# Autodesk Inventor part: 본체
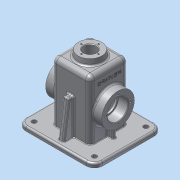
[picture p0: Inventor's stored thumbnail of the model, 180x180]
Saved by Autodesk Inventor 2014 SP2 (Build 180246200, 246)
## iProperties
Created: 2016-08
Part Number: 본체
Material: 알루미늄 6061
Document SubType Name: Modeling
Designer: user
Density: 2.71 g/cm^3
Appearance: 알루미늄 - 평지
Author: user
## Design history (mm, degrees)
sketch "스케치1"
  geometry: L1 (-32.5, 32.5)-(32.5, 32.5); L2 (32.5, 32.5)-(32.5, -32.5); L3 (32.5, -32.5)-(-32.5, -32.5); L4 (-32.5, -32.5)-(-32.5, 32.5); L5 (-32.5, 32.5)-(32.5, -32.5); L6 (32.5, 32.5)-(-32.5, -32.5); 1 further point
  constraints: 12 end point, 2 midpoint, 2 parallel, 1 horizontal, 1 perpendicular
  dimensions: "d0" = 65 distance of L2.end L3.end; "d1" = 65 distance of L1.end L2.end
extrude "돌출1" new body sketch "스케치1" distance "d2" = 100; taper "d3" = 0 deg
sketch "스케치2"
  geometry: L1 (-65, 57.5)-(65, 57.5); L2 (65, 57.5)-(65, -57.5); L3 (65, -57.5)-(-65, -57.5); L4 (-65, -57.5)-(-65, 57.5); L5 (-65, 57.5)-(65, -57.5); L6 (65, 57.5)-(-65, -57.5); 1 further point
  constraints: 12 end point, 2 midpoint, 2 parallel, 1 horizontal, 1 perpendicular
  dimensions: "d4" = 130 distance of L2.end L3.end; "d5" = 115 distance of L1.end L2.end
extrude "돌출2" join sketch "스케치2" distance "d6" = 10; taper "d7" = 0 deg
fillet "모깎기1" dims "d8" = 8
fillet "모깎기2" dims "d9" = 8
feature "쉘1" dims "d10" = 5
sketch "스케치3"
  geometry: L1 (35.5, -80)-(84.5, -80) reference; L2 (87.5, -77)-(87.5, -28) reference; L3 (84.5, -25)-(35.5, -25) reference; L4 (32.5, -28)-(32.5, -77) reference; L5 (120, -105)-(0, -105) reference; L6 (0, -105)-(0, 0) reference; L7 (0, 0)-(120, 0) reference; L8 (120, 0)-(120, -105) reference; A1 r 3 centre (84.5, -77) between (84.5, -80) and (87.5, -77) reference; A2 r 3 centre (84.5, -28) between (87.5, -28) and (84.5, -25) reference; A3 r 3 centre (35.5, -28) between (35.5, -25) and (32.5, -28) reference; A4 r 3 centre (35.5, -77) between (32.5, -77) and (35.5, -80) reference; 1 further point
extrude "돌출3" join sketch "스케치3" stored distance "d11" = 10; taper "d12" = 0 deg
fillet "모깎기3" dims "d13" = 14
sketch "스케치4"
  geometry: L1 (-51, -57.5)-(51, -57.5) reference; L2 (65, -43.5)-(65, 43.5) reference; L3 (51, 57.5)-(-51, 57.5) reference; L4 (-65, 43.5)-(-65, -43.5) reference; L5 (-51, -52.5)-(51, -52.5); L6 (60, -43.5)-(60, 43.5); L7 (51, 52.5)-(-51, 52.5); L8 (-60, 43.5)-(-60, -43.5); A1 r 14 centre (51, -43.5) between (51, -57.5) and (65, -43.5) reference; A2 r 14 centre (51, 43.5) between (65, 43.5) and (51, 57.5) reference; A3 r 14 centre (-51, 43.5) between (-51, 57.5) and (-65, 43.5) reference; A4 r 14 centre (-51, -43.5) between (-65, -43.5) and (-51, -57.5) reference; A5 r 9 centre (51, -43.5) between (51, -52.5) and (60, -43.5); A6 r 9 centre (51, 43.5) between (60, 43.5) and (51, 52.5); A7 r 9 centre (-51, 43.5) between (-51, 52.5) and (-60, 43.5); A8 r 9 centre (-51, -43.5) between (-60, -43.5) and (-51, -52.5); 1 further point
  constraints: 8 end point, 8 point on circle, 4 centre point, 7 other
  dimensions: "d14" = 5 distance between parallel lines of L4 L8
extrude "돌출4" cut sketch "스케치4" distance "d15" = 3; taper "d16" = 0 deg
fillet "모깎기4" dims "d17" = 3
node "작업 평면1"
sketch "스케치5"
  geometry: C1 r 20 at (0, 0); 1 further point
  constraints: 1 centre point, 1 coincident
  dimensions: "d19" = 40 diameter of C1
extrude "돌출5" join sketch "스케치5" stored distance "d20" = 3; taper "d21" = 7 deg
hole "구멍1" diameter "d24" = 21; stored, may be unused: countersink angle "d28" = 90 deg, drill point angle "d30" = 118 deg; dims "d22" = 10, "d23" = 10, "d25" = 6, "d26" = 4, "d27" = 2, "d29" = 8
fillet "모깎기5" dims "d31" = 3
chamfer "모따기1" distance "d32" = 1; stored, may be unused: second distance "d33" = 2, angle "d34" = 45 deg
node "작업 평면2"
sketch "스케치7"
  geometry: L1 (10, 49)-(10, 0) reference; C1 r 27.5 at (-45, 24.5); 1 further point
  constraints: 1 centre point, 1 horizontal alignment
  dimensions: "d38" = 55 diameter of C1; "d39" = 55 distance from line of L1 C1.centre
extrude "돌출6" join sketch "스케치7" stored distance "d40" = 3; taper "d41" = 0 deg
hole "구멍2" diameter "d45" = 30; stored, may be unused: countersink angle "d49" = 90 deg, drill point angle "d51" = 118 deg; dims "d43" = 10, "d44" = 10, "d46" = 6, "d47" = 4, "d48" = 2, "d50" = 8
hole "구멍3" diameter "d54" = 35; stored, may be unused: countersink angle "d58" = 90 deg, drill point angle "d60" = 0 deg; dims "d52" = 10, "d53" = 10, "d55" = 6, "d56" = 4, "d57" = 2, "d59" = 17
fillet "모깎기7" dims "d61" = 0.3
chamfer "모따기2" distance "d62" = 1; stored, may be unused: second distance "d63" = 2, angle "d64" = 45 deg
fillet "모깎기8" dims "d65" = 0.3
chamfer "모따기3" distance "d66" = 1; stored, may be unused: second distance "d67" = 2, angle "d68" = 45 deg
sketch "스케치8"
  geometry: L1 (-47.5, 17.5)-(-32.5, 17.5) reference; L2 (51, 0)-(-51, 0) reference; L3 (-42.5, 17.5)-(-42.5, 0); L4 (-27.5, 92)-(-27.5, -10) reference; 1 further point
  constraints: 2 end point, 2 point on line, 1 perpendicular
  dimensions: "d69" = 15 distance from line of L4 L3.end
feature "리브1" sketch "스케치8" dims "d70" = 1, "d71" = 6, "d72" = 0, "d73" = 0, "d74" = 1, "d75" = 1
fillet "모깎기9" dims "d76" = 3
fillet "모깎기10" dims "d77" = 3
sketch "스케치9"
  geometry: L1 (-32.5, 92)-(-32.5, 0) reference; L2 (-54.5, 0)-(-43.5, 0) reference; L3 (-32.5, 60)-(-41.068, 60); L4 (-41.068, 60)-(-49.5, 0); L5 (-57.5, -3)-(-57.5, -7) reference; L6 (-52.5, -10)-(-43.5, -10) reference; 1 further point
  constraints: 4 end point, 2 point on line, 1 parallel
  dimensions: "d78" = 8 deg angle of L5 L4; "d79" = 70 distance from line of L6 L3.end; "d80" = 8 horizontal distance of L5.end L4.end
feature "리브2" sketch "스케치9" dims "d81" = 1, "d82" = 10, "d83" = 0, "d84" = 0, "d85" = 1, "d86" = 1
fillet "모깎기11" dims "d87" = 3
fillet "모깎기12" dims "d88" = 3
sketch "스케치10"
  geometry: 5 further points
  constraints: 2 horizontal alignment, 2 vertical alignment
  dimensions: "d89" = 102 distance of point (51, 43.5) point (-51, 43.5); "d90" = 87 distance of point (51, -43.5) point (51, 43.5); "d91" = 51 horizontal distance of point (0, 0) point (-51, 43.5); "d92" = 43.5 vertical distance of point (51, -43.5) point (0, 0)
hole "구멍4" sketch "스케치10" at (-51, 43.5), (51, 43.5), (51, -43.5), (-51, -43.5) diameter "d93" = 8; stored, may be unused: countersink angle "d97" = 90 deg, drill point angle "d99" = 0 deg; dims "d94" = 6, "d95" = 4, "d96" = 2, "d98" = 17
sketch "스케치11" dims "d100" = 29
  geometry: 3 further points
  constraints: 2 horizontal alignment, 1 coincident, 2 other
hole "구멍5" sketch "스케치11" at (14.5, 0) diameter "d101" = 2.459; stored, may be unused: countersink angle "d105" = 90 deg, drill point angle "d107" = 118 deg; dims "d102" = 7, "d103" = 4, "d104" = 2, "d106" = 9
sketch "스케치12" dims "d111" = 42
  geometry: A1 r 27.5 centre (0, 0) between (-16.379, 22.09) and (-16.379, -22.09) reference; 3 further points
  constraints: 3 horizontal alignment, 3 other
hole "구멍6" sketch "스케치12" at (-21, 0) diameter "d112" = 3.242; stored, may be unused: countersink angle "d116" = 90 deg, drill point angle "d118" = 118 deg; dims "d113" = 8, "d114" = 4, "d115" = 2, "d117" = 10
fillet "모깎기13" dims "d122" = 1
node "작업 평면3"
sketch "스케치13"
  geometry: L1 (0, -8)-(91, -8) reference; L2 (-18, 44.5)-(-18, 4.5) reference; 2 further points
  constraints: 1 other
  dimensions: "d124" = 32.5 distance from line of L1 point (8, 24.5); "d125" = 26 distance from line of L2 point (8, 24.5)
feature "엠보싱1" sketch "스케치13" dims "d126" = 0.5, "d127" = 0
node "솔리드1"
mirror "대칭1"
mirror "대칭2"
mirror "대칭3"
mirror "대칭4"
pattern_circular "원형 패턴1" dims angle "d109" = 360 deg
pattern_circular "원형 패턴2" dims angle "d120" = 360 deg
mirror "대칭5"
other parameters: "d37" = 15, "d123" = 10.5
